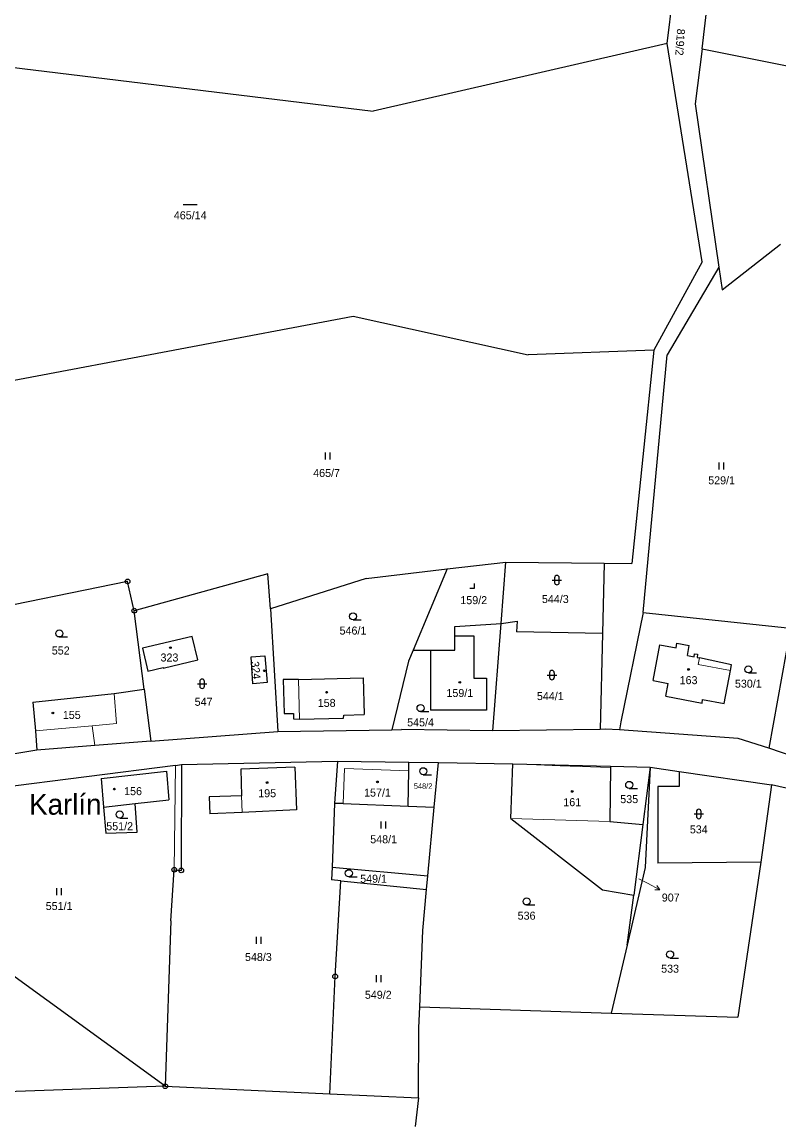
# Model space of a CAD drawing. Extents: x -739410 to -735662, y -942282 to -940043.
# Drawn here: x -737083.6 to -736922.9, y -941815.8 to -941581.8 of the extents above; entities that cross this region are included whole.
import ezdxf
from ezdxf.enums import TextEntityAlignment as Align

# ---------------------------------------------------------------- set-up
doc = ezdxf.new("R2010")
doc.units = 0
doc.header["$LTSCALE"] = 0.68
for name, color, linetype, lineweight in [('1', 7, 'Continuous', 25), ('3', 7, 'Continuous', 25), ('4', 7, 'Continuous', 13), ('5', 7, 'Continuous', 25), ('7', 7, 'Continuous', 13), ('8', 7, 'Continuous', 25)]:
    doc.layers.add(name, color=color, linetype=linetype, lineweight=lineweight)
doc.layers.add('2', color=7, linetype='Continuous')

msp = doc.modelspace()

# ---------------------------------------------------------------- linework, layer by layer
at = {"layer": '1'}
for p, q in [((-736939.25, -941587.5), (-736929.86, -941506.52)), ((-736946.67, -941586.41), (-736940.72, -941538.83)), ((-737122.63, -941586.94), (-737009.06, -941600.75)), ((-736946.67, -941586.41), (-737009.06, -941600.75)), ((-736939.25, -941632.73), (-736946.67, -941586.41)), ((-736939.25, -941587.5), (-736940.74, -941599.19)), ((-736939.25, -941587.5), (-736915.52, -941592.28)), ((-736940.74, -941599.19), (-736935.67, -941633.9)), ((-736934.97, -941638.72), (-736922.61, -941628.99)), ((-736939.25, -941632.73), (-736949.47, -941651.52)), ((-736935.67, -941633.9), (-736946.67, -941652.48)), ((-736935.67, -941633.9), (-736934.97, -941638.72)), ((-737086.74, -941658.17), (-737013.29, -941644.33)), ((-737013.29, -941644.33), (-736976.17, -941652.51)), ((-736949.47, -941651.52), (-736976.17, -941652.51)), ((-736949.47, -941651.52), (-736954.18, -941696.85)), ((-736951.78, -941707.21), (-736946.67, -941652.48)), ((-737010.55, -941699.98), (-736993.32, -941697.98)), ((-736993.32, -941697.98), (-737000.57, -941715.19)), ((-736993.32, -941697.98), (-736980.93, -941696.54)), ((-736981.92, -941709.58), (-736980.93, -941696.54)), ((-736980.93, -941696.54), (-736960.02, -941696.78)), ((-736960.02, -941696.78), (-736954.18, -941696.85)), ((-737031.42, -941699), (-737059.75, -941706.84)), ((-737030.87, -941706.47), (-737031.42, -941699)), ((-737010.55, -941699.98), (-737030.87, -941706.47)), ((-737057.64, -941723.52), (-737059.75, -941706.84)), ((-737030.87, -941706.47), (-737029.3, -941732.5)), ((-736951.78, -941707.21), (-736956.51, -941730.42)), ((-736951.78, -941707.21), (-736920.49, -941710.53)), ((-736991.7, -941710.19), (-736981.92, -941709.58)), ((-736991.7, -941712.19), (-736991.7, -941710.19)), ((-736983.66, -941732.38), (-736981.92, -941709.58)), ((-737047.5, -941712.3), (-737057.99, -941714.82)), ((-737046.26, -941717.3), (-737047.5, -941712.3)), ((-736991.7, -941715.19), (-736991.7, -941712.19)), ((-736991.7, -941712.19), (-736987.7, -941712.19)), ((-736987.7, -941712.19), (-736987.7, -941721.17)), ((-736960.4, -941711.72), (-736960.91, -941732.05)), ((-736920.49, -941710.53), (-736925.07, -941736.07)), ((-737057.99, -941714.82), (-737056.85, -941719.68)), ((-736949.62, -941721.69), (-736948.19, -941714.08)), ((-736948.19, -941714.08), (-736944.78, -941714.73)), ((-736944.78, -941714.73), (-736944.59, -941713.72)), ((-736944.59, -941713.72), (-736941.98, -941714.21)), ((-736942.38, -941716.37), (-736941.98, -941714.21)), ((-737053.62, -941719.02), (-737046.26, -941717.3)), ((-737034.97, -941716.63), (-737032.02, -941716.4)), ((-737034.56, -941722.37), (-737034.97, -941716.63)), ((-737032.02, -941716.4), (-737031.57, -941722.11)), ((-737000.57, -941715.19), (-737001.57, -941717.56)), ((-737000.57, -941715.19), (-736996.9, -941715.19)), ((-736996.9, -941715.19), (-736991.7, -941715.19)), ((-736996.9, -941715.19), (-736996.9, -941727.99)), ((-736942.38, -941716.37), (-736940.96, -941716.67)), ((-736940.96, -941716.67), (-736940.87, -941715.97)), ((-736940.87, -941715.97), (-736940.22, -941716.09)), ((-736940.22, -941716.09), (-736940.32, -941716.76)), ((-736940.32, -941716.76), (-736939.81, -941716.86)), ((-736933.04, -941718.33), (-736939.81, -941716.86)), ((-737056.85, -941719.68), (-737053.64, -941718.92)), ((-737053.64, -941718.92), (-737053.62, -941719.02)), ((-737001.57, -941717.56), (-737005.07, -941732.12)), ((-736934.55, -941726.55), (-736933.25, -941719.54)), ((-736933.25, -941719.54), (-736933.04, -941718.33)), ((-737031.57, -941722.11), (-737034.56, -941722.37)), ((-737024.88, -941721.48), (-737028.17, -941721.44)), ((-737028.17, -941721.44), (-737027.94, -941728.69)), ((-737024.88, -941721.48), (-737011.15, -941721.09)), ((-737011.15, -941721.09), (-737010.97, -941728.88)), ((-736987.7, -941721.17), (-736985, -941721.17)), ((-736985, -941721.17), (-736985, -941727.99)), ((-736949.62, -941721.69), (-736946.45, -941722.29)), ((-737081.31, -941726.29), (-737064.04, -941724.42)), ((-737064.04, -941724.42), (-737057.64, -941723.52)), ((-737057.64, -941723.52), (-737056.24, -941734.52)), ((-736946.95, -941724.99), (-736946.45, -941722.29)), ((-737081.31, -941726.29), (-737080.73, -941732.37)), ((-736946.95, -941724.99), (-736939.27, -941726.45)), ((-736939.27, -941726.45), (-736939.16, -941725.68)), ((-736939.16, -941725.68), (-736934.55, -941726.55)), ((-737027.94, -941728.69), (-737025.98, -941728.69)), ((-737025.98, -941728.69), (-737025.98, -941729.82)), ((-737015.36, -941729.64), (-737015.31, -941729.03)), ((-737015.31, -941729.03), (-737010.97, -941728.88)), ((-736985, -941727.99), (-736996.9, -941727.99)), ((-737025.98, -941729.82), (-737024.69, -941729.88)), ((-737024.69, -941729.88), (-737015.36, -941729.64)), ((-736956.51, -941730.42), (-736956.81, -941732.13)), ((-737080.73, -941732.37), (-737080.44, -941736.44)), ((-737056.24, -941734.52), (-737029.3, -941732.5)), ((-737029.3, -941732.5), (-737005.07, -941732.12)), ((-737005.07, -941732.12), (-737003.01, -941732.09)), ((-736983.66, -941732.38), (-737003.01, -941732.09)), ((-736960.91, -941732.05), (-736983.66, -941732.38)), ((-736959.85, -941732.03), (-736960.91, -941732.05)), ((-736956.81, -941732.13), (-736959.85, -941732.03)), ((-736931.59, -941733.96), (-736956.81, -941732.13)), ((-737068.14, -941735.5), (-737080.44, -941736.44)), ((-737056.24, -941734.52), (-737068.14, -941735.5)), ((-736925.07, -941736.07), (-736931.59, -941733.96)), ((-736919.49, -941737.93), (-736925.07, -941736.07)), ((-737080.44, -941736.44), (-737085.55, -941737.3)), ((-737051.02, -941739.69), (-737094.74, -941745.32)), ((-737051.02, -941739.69), (-737049.72, -941739.5)), ((-737049.72, -941739.5), (-737049.79, -941761.99)), ((-737049.72, -941739.5), (-737016.6, -941738.8)), ((-737025.66, -941740.06), (-737037.17, -941740.49)), ((-737037.17, -941740.49), (-737036.99, -941746.18)), ((-737025.66, -941740.06), (-737025.34, -941749.16)), ((-737016.6, -941738.8), (-737017.23, -941747.79)), ((-737016.6, -941738.8), (-737001.5, -941738.99)), ((-737001.48, -941740.85), (-737001.5, -941738.99)), ((-737001.5, -941738.99), (-736995.19, -941739.07)), ((-736996.08, -941748.53), (-736995.19, -941739.07)), ((-736995.19, -941739.07), (-736979.42, -941739.33)), ((-736979.86, -941750.95), (-736979.42, -941739.33)), ((-736979.42, -941739.33), (-736958.67, -941739.88)), ((-736958.67, -941740.15), (-736958.86, -941751.6)), ((-736958.67, -941739.88), (-736958.67, -941740.15)), ((-736958.67, -941739.88), (-736950.28, -941740.1)), ((-736950.28, -941740.1), (-736944.09, -941740.99)), ((-737066.81, -941742.46), (-737052.93, -941740.93)), ((-737066.81, -941742.46), (-737066.28, -941748.56)), ((-737052.93, -941740.93), (-737052.4, -941747.03)), ((-737001.66, -941748.36), (-737001.48, -941740.85)), ((-736944.09, -941740.99), (-736944.09, -941744.19)), ((-736944.09, -941740.99), (-736924.54, -941743.82)), ((-736944.09, -941744.19), (-736948.66, -941744.19)), ((-736948.66, -941744.19), (-736948.66, -941760.49)), ((-736924.54, -941743.82), (-736926.77, -941760.28)), ((-736895.3, -941750.34), (-736924.54, -941743.82)), ((-737066.28, -941748.56), (-737059.55, -941747.82)), ((-737059.55, -941747.82), (-737052.4, -941747.03)), ((-737059.17, -941753.9), (-737059.55, -941747.82)), ((-737036.99, -941746.18), (-737043.87, -941746.4)), ((-737043.87, -941746.4), (-737043.74, -941749.99)), ((-737017.23, -941747.79), (-737017.76, -941761.3)), ((-737015.44, -941747.79), (-737017.23, -941747.79)), ((-737015.44, -941747.79), (-737001.66, -941748.36)), ((-737066.28, -941748.56), (-737065.82, -941754.12)), ((-737036.84, -941749.68), (-737043.74, -941749.99)), ((-737025.34, -941749.16), (-737036.84, -941749.68)), ((-737001.66, -941748.36), (-736996.08, -941748.53)), ((-736997.45, -941763.16), (-736996.08, -941748.53)), ((-736979.86, -941750.95), (-736960.4, -941766.1)), ((-736958.86, -941751.6), (-736951.84, -941752.28)), ((-737065.82, -941754.12), (-737059.17, -941753.9)), ((-737052, -941772.7), (-737051.26, -941761.85)), ((-737051.26, -941761.85), (-737049.79, -941761.99)), ((-737017.76, -941761.3), (-737017.87, -941763.99)), ((-737017.76, -941761.3), (-736997.45, -941763.16)), ((-736926.77, -941760.28), (-736948.66, -941760.49)), ((-736926.77, -941760.28), (-736931.65, -941793.16)), ((-737015.93, -941764.19), (-737017.87, -941763.99)), ((-736997.72, -941766.07), (-736997.45, -941763.16)), ((-736998.54, -941774.74), (-736997.72, -941766.07)), ((-736960.4, -941766.1), (-736953.74, -941767.25)), ((-736955.16, -941777.85), (-736953.74, -941767.25)), ((-736999.16, -941790.98), (-736998.54, -941774.74)), ((-736955.16, -941777.85), (-736958.56, -941792.29)), ((-737018.24, -941809.42), (-737017.12, -941784.52)), ((-736999.33, -941795.46), (-736999.16, -941790.98)), ((-736999.16, -941790.98), (-736958.56, -941792.29)), ((-736958.56, -941792.29), (-736931.65, -941793.16)), ((-736999.45, -941810.26), (-736999.33, -941795.46)), ((-737053.19, -941807.82), (-737133.17, -941810.59)), ((-736999.45, -941810.26), (-737000.12, -941816.4))]:
    msp.add_line(p, q, dxfattribs=at)
for points in [[(-736960.02, -941696.78), (-736960.4, -941711.72), (-736978.62, -941711.36)], [(-737059.75, -941706.84), (-737061.16, -941700.64), (-737094.44, -941707.46)], [(-736981.92, -941709.58), (-736978.53, -941709.09), (-736978.62, -941711.36)], [(-736950.28, -941740.1), (-736951.36, -941761.38), (-736955.16, -941777.85)], [(-736950.28, -941740.1), (-736951.84, -941752.28), (-736953.74, -941767.25)], [(-737017.12, -941784.52), (-737015.93, -941764.19), (-736997.72, -941766.07)], [(-737052, -941772.7), (-737053.19, -941807.82), (-737091.33, -941780.13)], [(-737053.19, -941807.82), (-737018.24, -941809.42), (-736999.45, -941810.26)]]:
    msp.add_lwpolyline(points, dxfattribs=at)
at = {"layer": '3'}
for p, q in [((-737049.378, -941620.6), (-737046.378, -941620.6)), ((-737019.201, -941674.75), (-737019.201, -941673.25)), ((-737018.2, -941674.75), (-737018.2, -941673.25)), ((-736935.621, -941676.88), (-736935.621, -941675.38)), ((-736934.62, -941676.88), (-736934.62, -941675.38)), ((-736971.061, -941700.341), (-736969.059, -941700.341)), ((-736970.561, -941699.841), (-736970.561, -941700.842)), ((-736969.559, -941700.842), (-736969.559, -941699.841)), ((-737013.333, -941708.79), (-737011.583, -941708.79)), ((-737075.663, -941712.42), (-737073.913, -941712.42)), ((-737045.861, -941721.861), (-737045.861, -941722.862)), ((-737044.859, -941722.862), (-737044.859, -941721.861)), ((-736972.111, -941720.511), (-736970.109, -941720.511)), ((-736971.611, -941720.011), (-736971.611, -941721.012)), ((-736970.609, -941721.012), (-736970.609, -941720.011)), ((-736929.433, -941720.06), (-736927.683, -941720.06)), ((-737046.361, -941722.361), (-737044.359, -941722.361)), ((-736998.993, -941728.28), (-736997.243, -941728.28)), ((-736998.423, -941741.68), (-736996.673, -941741.68)), ((-736954.713, -941744.58), (-736952.963, -941744.58)), ((-736940.961, -941750.011), (-736938.959, -941750.011)), ((-736940.461, -941749.511), (-736940.461, -941750.512)), ((-736939.459, -941750.512), (-736939.459, -941749.511)), ((-737062.843, -941750.87), (-737061.093, -941750.87)), ((-737007.341, -941753.11), (-737007.341, -941751.61)), ((-737006.34, -941753.11), (-737006.34, -941751.61)), ((-737014.223, -941763.34), (-737012.473, -941763.34)), ((-737076.211, -941767.28), (-737076.211, -941765.78)), ((-737075.21, -941767.28), (-737075.21, -941765.78)), ((-736976.493, -941769.33), (-736974.743, -941769.33)), ((-737033.841, -941777.62), (-737033.841, -941776.12)), ((-737032.84, -941777.62), (-737032.84, -941776.12)), ((-736946.043, -941780.6), (-736944.293, -941780.6)), ((-737008.351, -941785.73), (-737008.351, -941784.23)), ((-737007.35, -941785.73), (-737007.35, -941784.23))]:
    msp.add_line(p, q, dxfattribs=at)
msp.add_lwpolyline([(-736988.561, -941702.09), (-736987.56, -941702.09), (-736987.56, -941701.09)], dxfattribs=at)
for centre in [(-737013.3329, -941708.0398), (-737075.6629, -941711.6698), (-736929.4329, -941719.3098), (-736998.9929, -941727.5298), (-736998.4229, -941740.9298), (-736954.7129, -941743.8298), (-737062.8429, -941750.1198), (-737014.2229, -941762.5898), (-736976.4929, -941768.5798), (-736946.0429, -941779.8498)]:
    msp.add_circle(centre, 0.75, dxfattribs=at)
for centre, start, end in [((-736970.06, -941699.8409), 0, 180), ((-736970.06, -941700.8409), 180, 359.98789), ((-736971.11, -941720.0109), 0, 180), ((-737045.36, -941721.8609), 0, 180), ((-736971.11, -941721.0109), 180, 359.98789), ((-737045.36, -941722.8609), 180, 359.98789), ((-736939.96, -941749.5109), 0, 180), ((-736939.96, -941750.5109), 180, 359.98789)]:
    msp.add_arc(centre, 0.5, start, end, dxfattribs=at)
at = {"layer": '4'}
for p, q in [((-736940.07, -941718.24), (-736939.81, -941716.86)), ((-736940.07, -941718.24), (-736933.25, -941719.54)), ((-737024.88, -941721.48), (-737024.69, -941729.88)), ((-737064.04, -941724.42), (-737063.5, -941730.79)), ((-737080.73, -941732.37), (-737068.71, -941731.27)), ((-737068.71, -941731.27), (-737063.5, -941730.79)), ((-737068.71, -941731.27), (-737068.14, -941735.5)), ((-737051.26, -941761.85), (-737051.02, -941739.69)), ((-737015.11, -941740.37), (-737015.44, -941747.79)), ((-737015.11, -941740.37), (-737001.48, -941740.85)), ((-736969.4, -941739.79), (-736979.42, -941739.33)), ((-736969.4, -941739.79), (-736958.67, -941740.15)), ((-737036.99, -941746.18), (-737036.84, -941749.68)), ((-736958.86, -941751.6), (-736979.86, -941750.95))]:
    msp.add_line(p, q, dxfattribs=at)
at = {"layer": '5'}
for centre in [(-737052.0668, -941714.6792), (-737032.1668, -941719.5992), (-736942.1268, -941719.3192), (-736990.6668, -941722.0492), (-737018.9268, -941724.1492), (-737077.0268, -941728.5592), (-737031.5568, -941743.3292), (-737008.1468, -941743.1992), (-737063.9768, -941744.7392), (-736966.8168, -941745.2292)]:
    msp.add_circle(centre, 0.175, dxfattribs=at)
at = {"layer": '7'}
msp.add_line((-736948.19, -941766.129), (-736948.839, -941765.217), dxfattribs=at)
msp.add_lwpolyline([(-736952.66, -941763.77), (-736950.84, -941764.72), (-736948.19, -941766.129), (-736949.31, -941766.101)], dxfattribs=at)
at = {"layer": '8'}
for centre, radius in [((-737061.16, -941700.6399), 0.5), ((-737061.16, -941700.6399), 0.0303), ((-737059.75, -941706.8399), 0.5), ((-737059.75, -941706.8399), 0.0303), ((-737051.26, -941761.8499), 0.5), ((-737051.26, -941761.8499), 0.0303), ((-737049.79, -941761.9899), 0.5), ((-737049.79, -941761.9899), 0.0303), ((-737017.12, -941784.5199), 0.5), ((-737017.12, -941784.5199), 0.0303), ((-737053.19, -941807.8199), 0.5), ((-737053.19, -941807.8199), 0.0303)]:
    msp.add_circle(centre, radius, dxfattribs=at)

# ---------------------------------------------------------------- texts
at = {"layer": '2'}
for s, rotation, p in [('819/2', 266, (-736944.746, -941586.0407)), ('324', 276, (-737034.8076, -941719.5787))]:
    msp.add_text(s, height=1.7, rotation=rotation, dxfattribs=at).set_placement(p, align=Align.CENTER)
for s, height, p in [('465/14', 1.7, (-737047.88, -941623.725)), ('465/7', 1.7, (-737018.94, -941678.445)), ('529/1', 1.7, (-736935.11, -941680.005)), ('159/2', 1.7, (-736987.71, -941705.455)), ('544/3', 1.7, (-736970.4, -941705.215)), ('546/1', 1.7, (-737013.34, -941711.915)), ('552', 1.7, (-737075.359, -941716.145)), ('323', 1.7, (-737052.289, -941717.635)), ('163', 1.7, (-736942.119, -941722.445)), ('530/1', 1.7, (-736929.44, -941723.185)), ('159/1', 1.7, (-736990.66, -941725.175)), ('544/1', 1.7, (-736971.46, -941725.825)), ('547', 1.7, (-737045.039, -941727.035)), ('158', 1.7, (-737018.919, -941727.275)), ('155', 1.7, (-737073.019, -941729.835)), ('545/4', 1.7, (-736999, -941731.405)), ('156', 1.7, (-737060.009, -941746.015)), ('195', 1.7, (-737031.549, -941746.455)), ('157/1', 1.7, (-737008.14, -941746.325)), ('548/2', 1.14, (-736998.459, -941744.655)), ('161', 1.7, (-736966.809, -941748.355)), ('535', 1.7, (-736954.719, -941747.705)), ('551/2', 1.7, (-737062.85, -941753.465)), ('534', 1.7, (-736939.959, -941754.135)), ('548/1', 1.7, (-737006.83, -941756.235)), ('549/1', 1.7, (-737008.97, -941764.615)), ('551/1', 1.7, (-737075.7, -941770.405)), ('907', 1.7, (-736945.909, -941768.605)), ('536', 1.7, (-736976.499, -941772.455)), ('548/3', 1.7, (-737033.41, -941781.235)), ('533', 1.7, (-736946.049, -941783.725)), ('549/2', 1.7, (-737007.97, -941789.255))]:
    msp.add_text(s, height=height, dxfattribs=at).set_placement(p, align=Align.CENTER)
at = {"layer": '7'}
msp.add_text('Karlín', height=4.4, dxfattribs=at).set_placement((-737074.379, -941750.16), align=Align.CENTER)

doc.saveas('drawing.dxf')
